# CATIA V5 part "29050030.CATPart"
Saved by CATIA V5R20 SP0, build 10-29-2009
Part number: 29050030
Definition: NONE
Nomenclature: 29050030
Source: Unknown
Description: 29050030
Bounding box of the stored display mesh (mm): x -15 to 44.548, y -39 to 73.548, z -29 to 29
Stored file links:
  C:\Users\Utente\Desktop\IO LAVORO\3D X SITO CF\X SITO\PLASTICA\RF1\29050030.CATPart
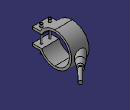
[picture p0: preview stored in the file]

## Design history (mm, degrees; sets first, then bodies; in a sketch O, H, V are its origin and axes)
Body1 "29050030" (main body)
  Solid1: solid without history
